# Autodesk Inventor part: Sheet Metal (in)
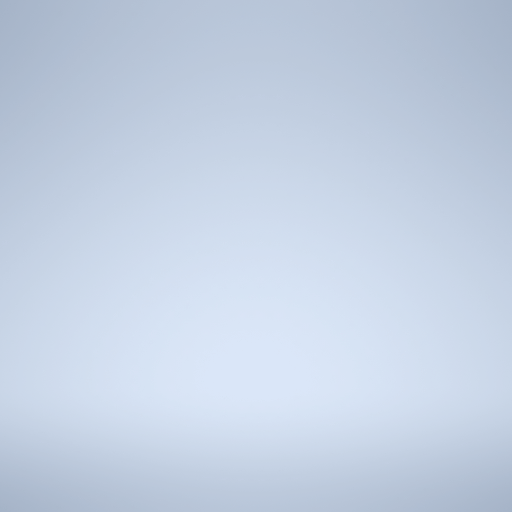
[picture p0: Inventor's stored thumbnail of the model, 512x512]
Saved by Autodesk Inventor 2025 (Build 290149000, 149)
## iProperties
Created: 2024-02
Part Number: Sheet Metal (in)
Material: Všeobecné
Document SubType Name: Sheet Metal
Density: 1 g/cm^3
Sheet Metal Rule: Výchozí
Appearance: Výchozí
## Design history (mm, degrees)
other parameters: "Tloušťka" = 3.048, "PoloměrOhybu" = 3.048 (= Tloušťka), "ŠířkaVýštipu" = 3.048 (= Tloušťka), "HloubkaVýštipu" = 1.524 (= 0.5 x Tloušťka), "VelikostRohovéhoVýštipu" = 12.192 (= 4 x Tloušťka), "SeamGap" = 0.00508, "MinimálníZbytek" = 6.096 (= 2 x Tloušťka), "PřechodovýPoloměr" = 3.048 (= PoloměrOhybu), "VelikostJacobihoPoloměru" = 3.048 (= PoloměrOhybu), "VelikostMezery" = 3.048 (= Tloušťka)
